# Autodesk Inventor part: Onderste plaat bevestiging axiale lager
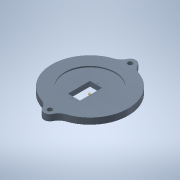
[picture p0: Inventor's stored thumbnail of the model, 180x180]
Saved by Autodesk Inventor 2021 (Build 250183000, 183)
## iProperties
Manager: Pierloot J.
Company: Emmaüs Bovenbouw Aalter
Created: 2015-08
Part Number: Onderste plaat bevestiging axiale lager
Material: S235
Catalog Web Link: http://emmausbovenbouw.op-weg.be/
Vendor: Emmaüsinstituut Bovenbouw Aalter
Document SubType Name: Modeling
Designer: Pierlootj
Engineer: Pierloot J.
Manufacturer: Standard
Standards Organization: Custom
Density: 7.86 g/cm^3
Appearance: Steel Blue
Title: Algemene titel
Subject: Specifieke titel
Author: Pierlootj
Keywords: Ruwe Ø xxxxx
Comments: Opmerking
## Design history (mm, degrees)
sketch "Sketch2"
  geometry: L1 (0, 0)-(0, 6); L2 (0, 6)-(-6, 6); L3 (-6, 6)-(6, 6); L4 (6, 6)-(6, -16.5); L5 (6, -16.5)-(-6, -16.5); L6 (-6, -16.5)-(-6, 6); L7 (6.3, 6.3)-(-6.3, 6.3); L8 (-6.3, 6.3)-(-6.3, -16.8); L9 (-6.3, -16.8)-(6.3, -16.8); L10 (6.3, -16.8)-(6.3, 6.3); C1 r 40 at (0, 0)
  constraints: 20 end point, 4 parallel, 3 perpendicular, 1 centre point, 1 coincident, 1 horizontal, 1 vertical, 3 other
  dimensions: "d15" = 6 distance of L1.start L1.end; "d16" = 6 distance of L1.end L2.end; "d17" = 12 distance of L4.end L5.end; "d18" = 22.5 distance of L3.end L4.end; "d19" = 80 diameter of C1; "d20" = 0.3 distance between parallel lines of L3 L7
extrude "Extrusion4" new body sketch "Sketch2" distance "d21" = 6.5; taper "d22" = 0 deg
sketch "Sketch3"
  geometry: L1 (-6.3, 6.3)-(6.3, 6.3) reference; L2 (0, 6.3)-(0, 8.25); L3 (6.3, -16.8)-(-6.3, -16.8) reference; L4 (0, -16.8)-(0, -18.75); C1 r 0.5 at (0, 8.25); C2 r 0.5 at (0, -18.75); 1 further point
  constraints: 4 end point, 2 centre point, 2 coincident, 2 midpoint, 2 vertical
  dimensions: "d23" = 1.95 distance of L2.start L2.end; "d24" = 1 diameter of C1; "d25" = 1.95 distance of L4.start L4.end; "d26" = 1 diameter of C2
extrude "Extrusion5" cut sketch "Sketch3" distance "d27" = 5.5; taper "d28" = 0 deg
sketch "Sketch5"
  geometry: C1 r 40 at (0, 0) reference; 1 further point
sketch "Sketch6"
  geometry: L1 (0, 0)-(0, -42); L2 (0, -42)-(0, 42); C1 r 2.5 at (0, 42); C2 r 6 at (0, 42); C3 r 2.5 at (0, -42); C4 r 6 at (0, -42)
  constraints: 4 centre point, 4 coincident, 4 end point, 1 point on line, 1 vertical
  dimensions: "d46" = 42 distance of L1.start L1.end; "d47" = 84 distance of L1.end L2.end; "d48" = 5 diameter of C1; "d49" = 12 diameter of C2; "d50" = 5 diameter of C3; "d51" = 12 diameter of C4
extrude "Extrusion9" join sketch "Sketch6" distance "d52" = 6.5; taper "d53" = 0 deg
extrude "Extrusion10" cut sketch "Sketch6" distance "d54" = 6.5; taper "d55" = 0 deg
fillet "Fillet2" dims "d56" = 12
sketch "Sketch8"
  geometry: C1 r 26.3 at (0, 0); 1 further point
  constraints: 1 centre point, 1 coincident
  dimensions: "d58" = 52.6 diameter of C1
extrude "Extrusion11" cut sketch "Sketch8" distance "d59" = 1.3; taper "d60" = 0 deg
body "Solid4"
